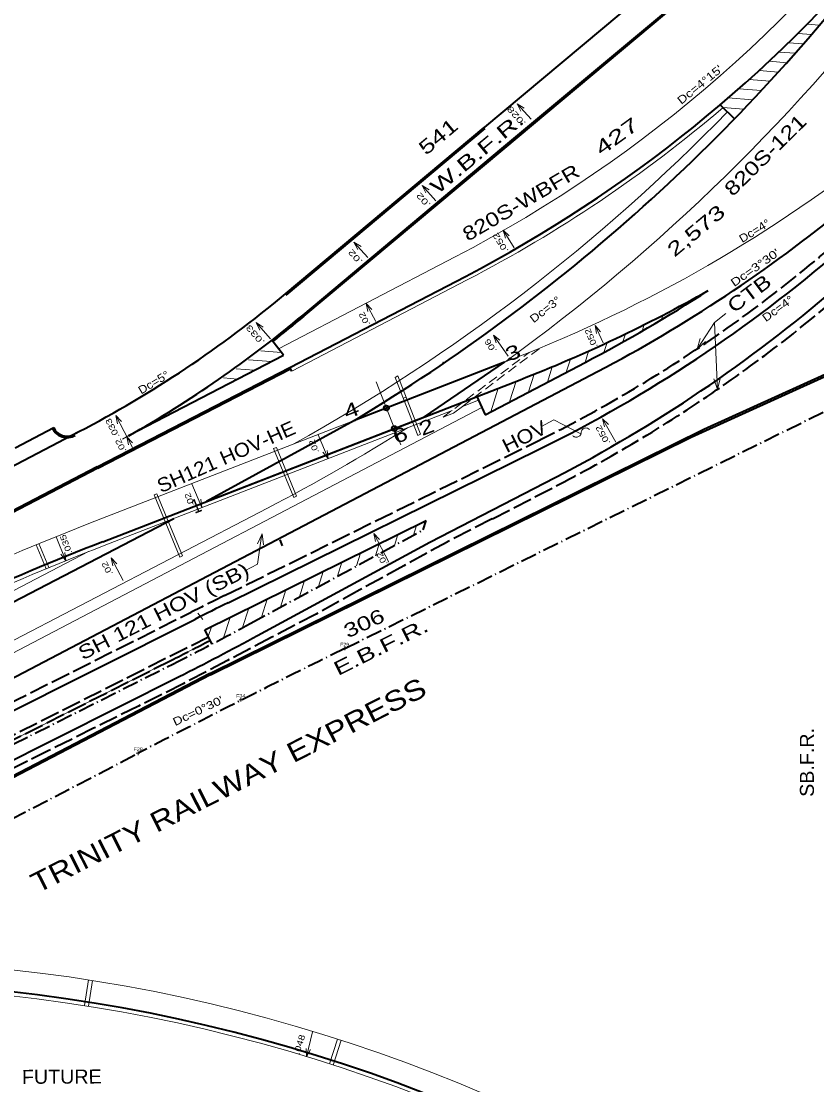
# Model space of a CAD drawing. Extents: x 2354993 to 2372084, y 6966390 to 6990057.
# Drawn here: x 2363431 to 2364227, y 6978118 to 6979180 of the extents above; entities that cross this region are included whole.
import ezdxf
from ezdxf.enums import TextEntityAlignment as Align

# ---------------------------------------------------------------- set-up
doc = ezdxf.new("R2010")
doc.units = 0
doc.header["$LTSCALE"] = 3.2
for name, pattern in [('DOT_DASHED', [7.7, 5, -1.2, 0.3, -1.2]), ('LONG_DASHED', [7.5, 6, -1.5]), ('MEDIUM_DASHED', [4.5, 3, -1.5])]:
    doc.linetypes.add(name, pattern=pattern)
for name, color, linetype, lineweight in [('1', 7, 'Continuous', 13), ('13', 7, 'Continuous', 13), ('17', 7, 'Continuous', 13), ('19', 7, 'Continuous', 13), ('2', 7, 'Continuous', 35), ('23', 7, 'Continuous', 13), ('28', 7, 'Continuous', 35), ('4', 7, 'Continuous', 13), ('5', 7, 'Continuous', 35), ('6', 7, 'Continuous', 35), ('63', 7, 'Continuous', 35), ('9', 7, 'Continuous', 13)]:
    doc.layers.add(name, color=color, linetype=linetype, lineweight=lineweight)

msp = doc.modelspace()

# ---------------------------------------------------------------- linework, layer by layer
at = {"layer": '1'}
for p, q in [((2363756.487, 6978553.588), (2363752.987, 6978553.588)), ((2363756.493, 6978553.591), (2363752.993, 6978553.591)), ((2363754.737, 6978555.338), (2363754.737, 6978551.838)), ((2363754.743, 6978555.341), (2363754.743, 6978551.841)), ((2363652.658, 6978502.288), (2363649.158, 6978502.288)), ((2363652.658, 6978502.288), (2363649.158, 6978502.288)), ((2363650.908, 6978504.038), (2363650.908, 6978500.538)), ((2363650.908, 6978504.038), (2363650.908, 6978500.538)), ((2363549.887, 6978448.9), (2363546.387, 6978448.9)), ((2363549.894, 6978448.903), (2363546.394, 6978448.903)), ((2363548.137, 6978450.65), (2363548.137, 6978447.15)), ((2363548.144, 6978450.653), (2363548.144, 6978447.153))]:
    msp.add_line(p, q, dxfattribs=at)
at = {"layer": '13'}
for p, q in [((2364124.311, 6978879.327), (2364135.635, 6978888.419)), ((2364124.311, 6978879.327), (2364107.051, 6978852.9)), ((2364124.311, 6978879.327), (2364127.473, 6978812.622)), ((2364107.051, 6978852.9), (2364110.158, 6978863.536)), ((2364107.051, 6978852.9), (2364115.294, 6978860.305)), ((2364127.472, 6978812.623), (2364123.858, 6978823.097)), ((2364127.473, 6978812.623), (2364129.916, 6978823.431)), ((2363667.59, 6978638.063), (2363671.897, 6978668.354)), ((2363672.046, 6978668.333), (2363667.62, 6978658.174)), ((2363672.047, 6978668.332), (2363673.633, 6978657.367)), ((2363667.59, 6978638.063), (2363654.762, 6978631.255))]:
    msp.add_line(p, q, dxfattribs=at)
for points in [[(2363950.859, 6978775.281), (2363963.619, 6978782.215), (2363990.892, 6978768.256)], [(2363999.577, 6978772.4), (2363998.454, 6978773.318), (2363997.504, 6978773.752), (2363996.636, 6978773.955), (2363995.824, 6978774), (2363995.058, 6978773.917), (2363994.332, 6978773.719), (2363993.644, 6978773.414), (2363992.997, 6978772.994), (2363992.396, 6978772.447), (2363991.85, 6978771.741), (2363991.388, 6978770.804), (2363991.214, 6978770.222), (2363991.098, 6978769.385), (2363990.979, 6978768.546), (2363990.806, 6978767.966), (2363990.674, 6978767.642), (2363990.343, 6978767.028), (2363990.06, 6978766.627), (2363989.798, 6978766.322), (2363989.197, 6978765.776), (2363988.55, 6978765.356), (2363987.863, 6978765.05), (2363987.137, 6978764.854), (2363986.37, 6978764.771), (2363985.559, 6978764.814), (2363984.69, 6978765.018), (2363984.046, 6978765.284), (2363983.739, 6978765.452), (2363983.238, 6978765.793), (2363982.618, 6978766.368)]]:
    msp.add_lwpolyline(points, dxfattribs=at)
at = {"layer": '17'}
for p, q in [((2363268.695, 6978481.439), (2363677.359, 6978693.821)), ((2363498.546, 6978222.377), (2363494.553, 6978196.824)), ((2363502.498, 6978221.759), (2363498.505, 6978196.207)), ((2363747.446, 6978163.351), (2363739.437, 6978138.405)), ((2363751.255, 6978162.128), (2363743.245, 6978137.182))]:
    msp.add_line(p, q, dxfattribs=at)
at = {"layer": '19'}
for p, q in [((2363927.094, 6979097.931), (2363930.771, 6979090.484)), ((2363927.094, 6979097.931), (2363934.149, 6979093.538)), ((2363941.005, 6979082.577), (2363927.094, 6979097.931)), ((2363832.045, 6979016.466), (2363835.722, 6979009.019)), ((2363832.045, 6979016.466), (2363839.1, 6979012.073)), ((2363845.956, 6979001.112), (2363832.045, 6979016.466)), ((2363913.032, 6978971.577), (2363915.358, 6978963.604)), ((2363913.032, 6978971.577), (2363919.215, 6978966.024)), ((2363924.06, 6978954.036), (2363913.032, 6978971.577)), ((2363763.983, 6978959.742), (2363767.66, 6978952.295)), ((2363763.983, 6978959.742), (2363771.038, 6978955.349)), ((2363777.894, 6978944.388), (2363763.983, 6978959.742)), ((2363776.001, 6978898.486), (2363777.835, 6978890.386)), ((2363776.001, 6978898.486), (2363781.833, 6978892.566)), ((2363785.936, 6978880.304), (2363776.001, 6978898.486)), ((2363666.116, 6978879.256), (2363669.793, 6978871.809)), ((2363666.116, 6978879.256), (2363673.171, 6978874.863)), ((2363680.616, 6978863.252), (2363666.116, 6978879.256)), ((2363903.322, 6978866.925), (2363909.75, 6978861.657)), ((2364005.199, 6978876.561), (2364006.371, 6978868.339)), ((2364005.199, 6978876.561), (2364010.533, 6978870.187)), ((2364012.986, 6978859.082), (2364005.199, 6978876.561)), ((2363525.767, 6978786.4), (2363527.497, 6978778.277)), ((2363525.767, 6978786.4), (2363531.523, 6978780.405)), ((2363542.615, 6978754.612), (2363525.767, 6978786.4)), ((2364012.378, 6978783.117), (2364014.392, 6978775.06)), ((2364012.378, 6978783.117), (2364018.341, 6978777.327)), ((2364025.8, 6978759.806), (2364012.378, 6978783.117)), ((2363532.44, 6978762.884), (2363539.021, 6978766.379)), ((2363536.944, 6978765.222), (2363538.674, 6978757.099)), ((2363536.944, 6978765.222), (2363542.7, 6978759.227)), ((2363728.247, 6978767.198), (2363738.051, 6978743.352)), ((2363738.051, 6978743.352), (2363732.905, 6978749.878)), ((2363738.051, 6978743.352), (2363737.118, 6978751.605)), ((2363601.957, 6978718.326), (2363611.761, 6978694.48)), ((2363611.761, 6978694.48), (2363610.828, 6978702.733)), ((2363466.118, 6978665.11), (2363475.922, 6978641.264)), ((2363783.747, 6978668.654), (2363785.477, 6978660.531)), ((2363783.747, 6978668.654), (2363789.503, 6978662.659)), ((2363798.92, 6978640.025), (2363783.747, 6978668.654)), ((2363475.922, 6978641.264), (2363470.776, 6978647.79)), ((2363475.922, 6978641.264), (2363474.989, 6978649.517)), ((2363521.224, 6978644.262), (2363522.954, 6978636.139)), ((2363521.224, 6978644.262), (2363526.98, 6978638.267)), ((2363533.298, 6978621.481), (2363521.224, 6978644.262)), ((2363613.023, 6978582.513), (2363607.877, 6978589.039)), ((2363716.338, 6978145.542), (2363716.086, 6978153.85))]:
    msp.add_line(p, q, dxfattribs=at)
for points in [[(2363918.021, 6978845.743), (2363903.322, 6978866.925), (2363906.006, 6978859.066)], [(2363722.648, 6978170.541), (2363716.338, 6978145.542), (2363720.499, 6978152.731)]]:
    msp.add_lwpolyline(points, dxfattribs=at)
at = {"layer": '2'}
for p, q in [((2363695.384, 6978907.983), (2364072.128, 6979223.133)), ((2363911.877, 6979053.229), (2364089.77, 6979202.039)), ((2363912.839, 6979052.078), (2364090.732, 6979200.888)), ((2364130.07, 6979096.947), (2364144.412, 6979083.009)), ((2363695.379, 6978907.981), (2363894.233, 6979074.323)), ((2363696.341, 6978906.829), (2363895.195, 6979073.173)), ((2363713.023, 6978886.887), (2363911.877, 6979053.229)), ((2363713.984, 6978885.737), (2363912.839, 6979052.079)), ((2363699.848, 6978834.335), (2363875.325, 6978925.541)), ((2363693.391, 6978846.757), (2363681.807, 6978861.611)), ((2363538.707, 6978766.357), (2363693.391, 6978846.757)), ((2363038.234, 6978322.559), (2364007.4, 6978830.292)), ((2363507.097, 6978735.295), (2363699.848, 6978834.335)), ((2363507.783, 6978733.961), (2363700.534, 6978833.001)), ((2363701.693, 6978830.785), (2363699.848, 6978834.335)), ((2363512.767, 6978660.249), (2363930.064, 6978822.286)), ((2363886.744, 6978805.465), (2363895.028, 6978787.227)), ((2358006.591, 6975920.846), (2363488.891, 6978770.331)), ((2363638.158, 6978599.34), (2363950.965, 6978753.691)), ((2363833.285, 6978672.206), (2363836.223, 6978681.461)), ((2362811.106, 6978184.667), (2363604.71, 6978582.7)), ((2363622.04, 6978558.072), (2363614.958, 6978572.167)), ((2363143.211, 6978301.576), (2363589.111, 6978525.607))]:
    msp.add_line(p, q, dxfattribs=at)
at = {"layer": '2', "linetype": 'LONG_DASHED'}
for p, q in [((2363634.618, 6978606.514), (2363947.425, 6978760.865)), ((2363902.287, 6978683.113), (2363968.888, 6978717.538)), ((2363902.235, 6978683.214), (2363857.739, 6978660.407)), ((2363857.675, 6978660.373), (2363813.85, 6978636.301)), ((2363813.786, 6978636.267), (2363769.961, 6978612.195)), ((2363769.897, 6978612.161), (2363726.072, 6978588.089)), ((2362775.435, 6978175.726), (2363601.123, 6978589.851)), ((2363726.072, 6978588.089), (2363681.803, 6978564.844)), ((2363618.55, 6978565.019), (2362905.562, 6978206.794)), ((2363681.803, 6978564.844), (2363637.534, 6978541.599)), ((2363135.13, 6978317.66), (2363581.03, 6978541.691)), ((2363637.533, 6978541.601), (2363593.264, 6978518.356)), ((2363593.265, 6978518.356), (2363548.487, 6978496.107)), ((2363548.488, 6978496.107), (2363503.71, 6978473.858)), ((2363503.711, 6978473.858), (2363458.933, 6978451.609)), ((2363458.934, 6978451.609), (2363414.156, 6978429.36))]:
    msp.add_line(p, q, dxfattribs=at)
at = {"layer": '2'}
msp.add_lwpolyline([(2363667.497, 6978566.51), (2363839.951, 6978659.895), (2363965.216, 6978724.645)], dxfattribs=at)
for centre, radius, start, end in [((2362792.03, 6980397.363), 1885.859, 301.04574, 322.89258), ((2363247.127, 6980134.169), 1362.136, 297.46364, 320.4266), ((2363323.326, 6980025.663), 1418.395, 296.26348, 310.78211), ((2363406.512, 6980170.6), 1446.395, 291.22127, 299.46693), ((2363298.192, 6980015.937), 1453.395, 297.31887, 310.6767), ((2362961.103, 6979785.775), 1144.416, 297.46365, 309.91281), ((2362961.101, 6979785.775), 1171.963, 299.53559, 309.91255), ((2362961.101, 6979785.775), 1173.462, 307.94874, 309.91255), ((2364544.669, 6976002.774), 2850.789, 111.22127, 117.46089), ((2366179.689, 6973448.679), 5743.578, 116.26348, 116.63614), ((2362296.691, 6981097.975), 2878.789, 296.67607, 298.43586)]:
    msp.add_arc(centre, radius, start, end, dxfattribs=at)
at = {"layer": '2', "linetype": 'LONG_DASHED'}
for centre, radius, start, end in [((2363323.326, 6980025.663), 1410.395, 296.26348, 313.14638), ((2363298.192, 6980015.937), 1461.395, 297.31887, 312.20163), ((2366179.689, 6973448.679), 5751.578, 116.26348, 116.63614), ((2362296.691, 6981097.975), 2860.789, 296.67607, 297.55731)]:
    msp.add_arc(centre, radius, start, end, dxfattribs=at)
at = {"layer": '23'}
msp.add_line((2363928.757, 6978804.834), (2363928.732, 6978804.883), dxfattribs=at)
at = {"layer": '28'}
msp.add_line((2363692.6, 6978656.074), (2363690.033, 6978662.131), dxfattribs=at)
at = {"layer": '4'}
for p, q in [((2364159.109, 6979122.195), (2364179.814, 6979120.444)), ((2364169.006, 6979131.395), (2364188.329, 6979129.761)), ((2364148.639, 6979113.046), (2364171.194, 6979111.139)), ((2364138.169, 6979103.897), (2364162.465, 6979101.843)), ((2364132.776, 6979094.317), (2364153.623, 6979092.553)), ((2363688.388, 6978853.171), (2363865.179, 6978945.061)), ((2363701.693, 6978830.785), (2363877.17, 6978921.991)), ((2363670.716, 6978851.185), (2363691.218, 6978849.543)), ((2363658.618, 6978842.121), (2363681.022, 6978840.327)), ((2363633.508, 6978824.067), (2363647.572, 6978822.941)), ((2363646.219, 6978833.081), (2363664.295, 6978831.633))]:
    msp.add_line(p, q, dxfattribs=at)
for centre, radius, start, end in [((2363247.127, 6980134.169), 1340.136, 297.46364, 325.00264), ((2362792.03, 6980397.361), 1919.859, 305.78394, 323.02193), ((2362792.03, 6980397.363), 1875.859, 299.08835, 315.81698), ((2363247.127, 6980134.169), 1366.136, 297.46364, 310.42224), ((2362792.03, 6980397.361), 1919.859, 297.46086, 302.28095)]:
    msp.add_arc(centre, radius, start, end, dxfattribs=at)
at = {"layer": '5', "lineweight": 13}
for p, q in [((2364216.798, 6979177.532), (2364229.349, 6979176.471)), ((2364207.578, 6979168.276), (2364221.346, 6979167.111)), ((2364198.193, 6979159.034), (2364213.245, 6979157.761)), ((2364189.442, 6979149.738), (2364205.042, 6979148.419)), ((2364179.34, 6979140.558), (2364196.737, 6979139.086)), ((2364091.724, 6978896.81), (2364090.85, 6978894.042)), ((2364054.093, 6978877.273), (2364052.06, 6978870.836)), ((2364072.843, 6978886.833), (2364071.375, 6978882.184)), ((2364035.469, 6978868.114), (2364032.897, 6978859.975)), ((2364016.964, 6978859.339), (2364013.878, 6978849.575)), ((2363998.577, 6978850.935), (2363994.993, 6978839.597)), ((2363504.803, 6978680.758), (2363922.1, 6978842.795)), ((2363852.973, 6978839.977), (2363852.165, 6978837.688)), ((2363962.138, 6978835.184), (2363957.29, 6978819.845)), ((2363980.304, 6978842.888), (2363976.143, 6978829.722)), ((2363944.076, 6978827.812), (2363938.437, 6978809.968)), ((2363908.183, 6978813.789), (2363900.732, 6978790.215)), ((2363926.115, 6978820.752), (2363919.585, 6978800.092)), ((2363244.971, 6978455.701), (2363891.715, 6978794.521)), ((2363872.294, 6978795.563), (2363888.401, 6978801.817)), ((2363514.215, 6978656.52), (2363861.967, 6978791.553)), ((2363826.447, 6978676.637), (2363823.35, 6978666.838)), ((2363807.809, 6978667.441), (2363804.378, 6978656.588)), ((2363789.173, 6978658.245), (2363785.408, 6978646.338)), ((2363248.405, 6978520.48), (2363498.513, 6978650.46)), ((2363770.533, 6978649.048), (2363766.437, 6978636.089)), ((2363751.895, 6978639.85), (2363747.465, 6978625.838)), ((2363733.259, 6978630.655), (2363728.496, 6978615.589)), ((2363695.982, 6978612.261), (2363690.554, 6978595.09)), ((2363714.618, 6978621.457), (2363709.525, 6978605.339)), ((2363677.345, 6978603.064), (2363671.584, 6978584.84)), ((2363658.704, 6978593.866), (2363652.612, 6978574.59)), ((2363640.067, 6978584.67), (2363633.642, 6978564.34)), ((2363621.409, 6978575.408), (2363618.289, 6978565.537)), ((2363135.13, 6978317.66), (2363581.03, 6978541.691))]:
    msp.add_line(p, q, dxfattribs=at)
at = {"layer": '5'}
for p, q in [((2363895.028, 6978787.227), (2363994.993, 6978839.597)), ((2363255.18, 6978436.214), (2364007.4, 6978830.292)), ((2364101.183, 6978764.916), (2364238.257, 6978827.035)), ((2364113.723, 6978772.795), (2364238.524, 6978829.352)), ((2363425.177, 6978754.243), (2363463.775, 6978774.478)), ((2363620.009, 6978528.496), (2364113.723, 6978772.795)), ((2363482.757, 6978767.142), (2363488.89, 6978770.33)), ((2363620.695, 6978527.162), (2364101.183, 6978764.916)), ((2362654.988, 6978292.473), (2363507.292, 6978735.395)), ((2362655.626, 6978291.114), (2363508.018, 6978734.082)), ((2362391.142, 6978063.692), (2363583.984, 6978683.611)), ((2363614.958, 6978572.167), (2363836.223, 6978681.461)), ((2363620.009, 6978528.496), (2363045.424, 6978230.005)), ((2363620.695, 6978527.162), (2363049.66, 6978230.516))]:
    msp.add_line(p, q, dxfattribs=at)
at = {"layer": '5', "lineweight": 13}
for centre, radius, start, end in [((2363406.512, 6980170.6), 1424.395, 291.22127, 308.69896), ((2364544.669, 6976002.774), 2872.789, 111.22127, 117.46089), ((2364544.669, 6976002.774), 2846.789, 111.22127, 117.46089), ((2362296.691, 6981097.975), 2860.789, 296.67607, 297.55731), ((2362823.255, 6979494.499), 2021.91, 312.68984, 326.1095), ((2363244.672, 6976597.082), 1645.014, 38.12295, 103.3303), ((2363244.672, 6976597.082), 1619.014, 38.12295, 103.3303)]:
    msp.add_arc(centre, radius, start, end, dxfattribs=at)
at = {"layer": '5'}
for centre, radius, start, end in [((2363336.186, 6980111.513), 1446.395, 297.64942, 309.4527), ((2363333.422, 6980115.951), 1437.622, 297.39902, 303.07689), ((2362961.102, 6979785.775), 1144.416, 297.46365, 309.91255), ((2363476.995, 6978780.281), 15.938, 203.70124, 301.18072), ((2363476.995, 6978780.281), 14.438, 203.70124, 301.18072), ((2363244.672, 6976597.082), 1623.014, 38.12295, 103.3303)]:
    msp.add_arc(centre, radius, start, end, dxfattribs=at)
at = {"layer": '6', "linetype": 'DOT_DASHED'}
for p, q in [((2363754.737, 6978553.588), (2364601.335, 6978971.879)), ((2363754.737, 6978553.588), (2364596.754, 6978969.616)), ((2363660.831, 6978578.821), (2363833.285, 6978672.206)), ((2363136.926, 6978314.086), (2363582.826, 6978538.117)), ((2360272.717, 6976747.357), (2363548.144, 6978448.903)), ((2360272.718, 6976747.358), (2363548.137, 6978448.9)), ((2360272.718, 6976747.358), (2363548.137, 6978448.9))]:
    msp.add_line(p, q, dxfattribs=at)
at = {"layer": '6', "linetype": 'MEDIUM_DASHED', "lineweight": 13}
for p, q in [((2363853.114, 6978784.897), (2363939.034, 6978849.495)), ((2363872.294, 6978795.563), (2363949.948, 6978853.947))]:
    msp.add_line(p, q, dxfattribs=at)
at = {"layer": '6', "lineweight": 13}
for p, q in [((2363805.233, 6978824.449), (2363807.803, 6978826.119)), ((2363827.758, 6978766.441), (2363805.233, 6978824.449)), ((2363830.432, 6978767.843), (2363807.803, 6978826.119)), ((2363816.066, 6978804.84), (2363813.269, 6978803.754)), ((2363863.441, 6978788.907), (2363872.294, 6978795.563)), ((2363853.114, 6978784.897), (2363863.441, 6978788.907)), ((2363827.758, 6978766.441), (2363830.432, 6978767.843)), ((2363683.58, 6978753.396), (2363686.378, 6978754.482)), ((2363683.58, 6978753.396), (2363703.838, 6978704.436)), ((2363686.378, 6978754.482), (2363706.492, 6978705.869)), ((2363564.232, 6978707.053), (2363567.029, 6978708.139)), ((2363564.232, 6978707.053), (2363589.91, 6978644.993)), ((2363703.838, 6978704.436), (2363706.492, 6978705.869)), ((2363446.294, 6978657.296), (2363456.235, 6978633.272)), ((2363449.067, 6978658.442), (2363459.008, 6978634.417))]:
    msp.add_line(p, q, dxfattribs=at)
msp.add_lwpolyline([(2363567.029, 6978708.139), (2363592.582, 6978646.382), (2363589.91, 6978644.993)], dxfattribs=at)
at = {"layer": '6', "linetype": 'DOT_DASHED'}
for centre, radius, start, end in [((2362296.691, 6981097.975), 2864.789, 296.67607, 298.43586), ((2368830.754, 6968280.015), 11459.156, 116.29328, 117.45135)]:
    msp.add_arc(centre, radius, start, end, dxfattribs=at)
at = {"layer": '63', "lineweight": 13}
msp.add_line((2363810.651, 6978757.145), (2363786.194, 6978820.13), dxfattribs=at)
at = {"layer": '63'}
msp.add_line((2363764.611, 6978781.642), (2363616.642, 6978700.584), dxfattribs=at)
msp.add_lwpolyline([(2363616.642, 6978700.584), (2363834.48, 6978785.171), (2363914.559, 6978839.867), (2363764.611, 6978781.642)], dxfattribs=at)
for centre in [(2363796.353, 6978793.967), (2363804.317, 6978773.458)]:
    msp.add_circle(centre, 2.5, dxfattribs=at)
at = {"layer": '9'}
msp.add_arc((2360722.521, 6984327.136), 5729.573, 359.50797, 359.50797, dxfattribs=at)

# ---------------------------------------------------------------- texts
at = {"layer": '13'}
for s, height, rotation, width, p in [('541', 14, 39.872, 1.4, (2363835.916, 6979045.85)), ('W.B.F.R.', 14, 39.604, 1.5, (2363847.432, 6979006.886)), ('427', 14, 35.998, 1.55, (2364011.217, 6979045.622)), ('820S-121', 14, 44.651, 1.3, (2364142.504, 6979004.629)), ('820S-WBFR', 14, 30.36, 1.25, (2363877.779, 6978960.054)), ('2,573', 14, 39.872, 1.45, (2364084.325, 6978944.101)), ('CTB', 14, 36.829, 1.3, (2364143.802, 6978888.203)), ('HOV', 14, 26.59, 1.15, (2363916.601, 6978748.75)), ('SH121 HOV-HE', 14, 23.865, 1.1, (2363570.985, 6978708.718)), ('SH 121 HOV (SB)', 14, 27.086, 1.25, (2363492.872, 6978541.606)), ('306', 14, 24.683, 1.35, (2363757.765, 6978563.639)), ('E.B.F.R.', 14, 26.495, 1.45, (2363748.056, 6978525.975)), ('TRINITY RAILWAY EXPRESS', 20, 26.985, 1.2, (2363447.53, 6978308.55)), ('SB.F.R.', 14, 90.062, 1.05, (2364223.754, 6978405.383))]:
    msp.add_text(s, height=height, rotation=rotation, dxfattribs=dict(at, width=width)).set_placement(p)
at = {"layer": '13', "width": 1.05}
msp.add_text('FUTURE', height=14, rotation=0.302, dxfattribs=at).set_placement((2363471.904, 6978118.726), align=Align.CENTER)
at = {"layer": '17'}
for s, rotation, width, p in [("Dc=4°15'", 39.192, 1.25, (2364091.184, 6979096.857)), ('Dc=4°', 31.442, 1.15, (2364152.009, 6978958.787)), ("Dc=3°30'", 35.132, 1.3, (2364144.051, 6978914.755)), ('Dc=3°', 37.449, 1.2, (2363943.524, 6978878.531)), ('Dc=4°', 36.1, 1.2, (2364175.714, 6978879.656)), ('Dc=5°', 30.975, 1.15, (2363551.245, 6978807.403)), ("Dc=0°30'", 25.548, 1.25, (2363585.22, 6978476.002))]:
    msp.add_text(s, height=8, rotation=rotation, dxfattribs=dict(at, width=width)).set_placement(p)
at = {"layer": '19'}
for s, height, rotation, width, p in [('.028', 6, 131.299, 1.5, (2363936.266, 6979078.866)), ('.02', 6, 131.299, 1.5, (2363841.217, 6978997.401)), ('.052', 6, 121.279, 1.4, (2363918.746, 6978951.207)), ('.02', 6, 131.299, 1.5, (2363773.155, 6978940.677)), ('.02', 6, 117.775, 1.3, (2363780.46, 6978877.805)), ('.033', 6, 131.299, 1.5, (2363675.288, 6978860.191)), ('.052', 6, 113.136, 1.3, (2364007.796, 6978855.545)), ('.06', 6, 123.88, 1.35, (2363907.187, 6978851.421)), ('.033', 6, 117.046, 1.35, (2363529.963, 6978765.664)), ('.052', 6, 119.055, 1.35, (2364020.576, 6978759.048)), ('.02', 6, 117.046, 1.3, (2363536.734, 6978751.229)), ('.02', 5.999, 110.961, 1.25, (2363729.22, 6978750.076)), ('.02', 5.999, 110.961, 1.25, (2363604.815, 6978696.885)), ('.035', 5.999, 110.961, 1.3, (2363482.514, 6978649.258)), ('.02', 6, 117.046, 1.3, (2363797.954, 6978638.161)), ('.02', 6, 117.046, 1.3, (2363523.217, 6978628.408)), ('.048', 5.999, 72.722, 1.3, (2363709.268, 6978147.314))]:
    msp.add_text(s, height=height, rotation=rotation, dxfattribs=dict(at, width=width)).set_placement(p)
at = {"layer": '2'}
for s, width, p in [('F29', 1.1, (2363750.237, 6978555.791)), ('F34', 1.15, (2363646.237, 6978504.488)), ('F28', 1.15, (2363543.556, 6978451.103))]:
    msp.add_text(s, height=3.5, dxfattribs=dict(at, width=width)).set_placement(p)
at = {"layer": '63'}
for s, width, p in [('3', 1.4, (2363925.321, 6978842.701)), ('4', 1.45, (2363763.753, 6978785.27)), ('2', 1.4, (2363838.948, 6978768.499)), ('6', 1.35, (2363812.686, 6978760.473)), ('1', 0.85, (2363608.79, 6978689.722))]:
    msp.add_text(s, height=14, rotation=21.221, dxfattribs=dict(at, width=width)).set_placement(p, align=Align.CENTER)

doc.saveas('drawing.dxf')
